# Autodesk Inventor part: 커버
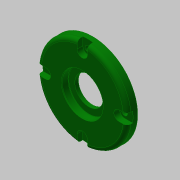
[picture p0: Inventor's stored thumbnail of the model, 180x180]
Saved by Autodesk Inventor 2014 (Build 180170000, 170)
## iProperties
Created: 2020-05
Part Number: 커버
Material: 알루미늄 6061
Document SubType Name: Modeling
Designer: mduedu
Density: 1 g/cm^3
Appearance: Dark Green
Author: mduedu
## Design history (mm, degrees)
sketch "스케치1"
  geometry: L1 (0, 0)-(8, 0); L2 (8, 0)-(8, 35); L3 (8, 35)-(0, 35); L4 (0, 35)-(0, 0); L5 (8, 0)-(12, 0); L6 (12, 0)-(12, 23.5); L7 (12, 23.5)-(8, 23.5); L8 (8, 23.5)-(8, 0)
  constraints: 16 end point, 4 parallel, 2 horizontal, 2 perpendicular
  dimensions: "d0" = 70 diameter of L3 L1; "d2" = 47 diameter of L7 L5; "d3" = 4 distance of L6.end L7.end; "d4" = 12 distance between parallel lines of L4 L6
revolve "회전1" sketch "스케치1" stored, may be unused: angle "d5" = 90 deg
hole "구멍1" diameter "d8" = 22; stored, may be unused: countersink angle "d12" = 90 deg, drill point angle "d14" = 118 deg; dims "d6" = 10, "d7" = 10, "d9" = 6, "d10" = 32, "d11" = 5.2, "d13" = 8
hole "구멍2" diameter "d17" = 40; stored, may be unused: countersink angle "d21" = 90 deg, drill point angle "d23" = 0 deg; dims "d15" = 10, "d16" = 10, "d18" = 6, "d19" = 32, "d20" = 5.2, "d22" = 4
fillet "모깎기1" dims "d24" = 3
fillet "모깎기2" dims "d25" = 3
fillet "모깎기3" dims "d26" = 0.3
chamfer "모따기1" distance "d27" = 0.5; stored, may be unused: second distance "d28" = 2, angle "d29" = 30 deg
chamfer "모따기2" distance "d30" = 1; stored, may be unused: second distance "d31" = 2, angle "d32" = 30 deg
sketch "스케치2" dims "d33" = 57
  geometry: L1 (-4, 28.5)-(4, 28.5); L2 (4, 28.5)-(4, 38.5); L3 (4, 38.5)-(-4, 38.5); L4 (-4, 38.5)-(-4, 28.5); 4 further points
  constraints: 8 end point, 2 horizontal alignment, 2 midpoint, 2 parallel, 2 vertical alignment, 1 coincident, 1 horizontal, 1 perpendicular, 6 other
  dimensions: "d34" = 8 distance between parallel lines of L2 L4; "d35" = 10 distance of point (0, 28.5) point (0, 38.5)
extrude "돌출1" cut sketch "스케치2" distance "d36" = 4.4; taper "d37" = 0 deg
sketch "스케치3"
  geometry: A1 r 4 centre (0, 28.5) between (-4, 28.5) and (4, 28.5) reference; 2 further points
  constraints: 1 coincident
hole "구멍3" sketch "스케치3" at (0, 28.5) diameter "d38" = 4.5; stored, may be unused: countersink angle "d42" = 90 deg, drill point angle "d44" = 0 deg; dims "d39" = 6, "d40" = 32, "d41" = 5.2, "d43" = 4
node "솔리드1"
pattern_circular "원형 패턴1" dims angle "d46" = 360 deg
